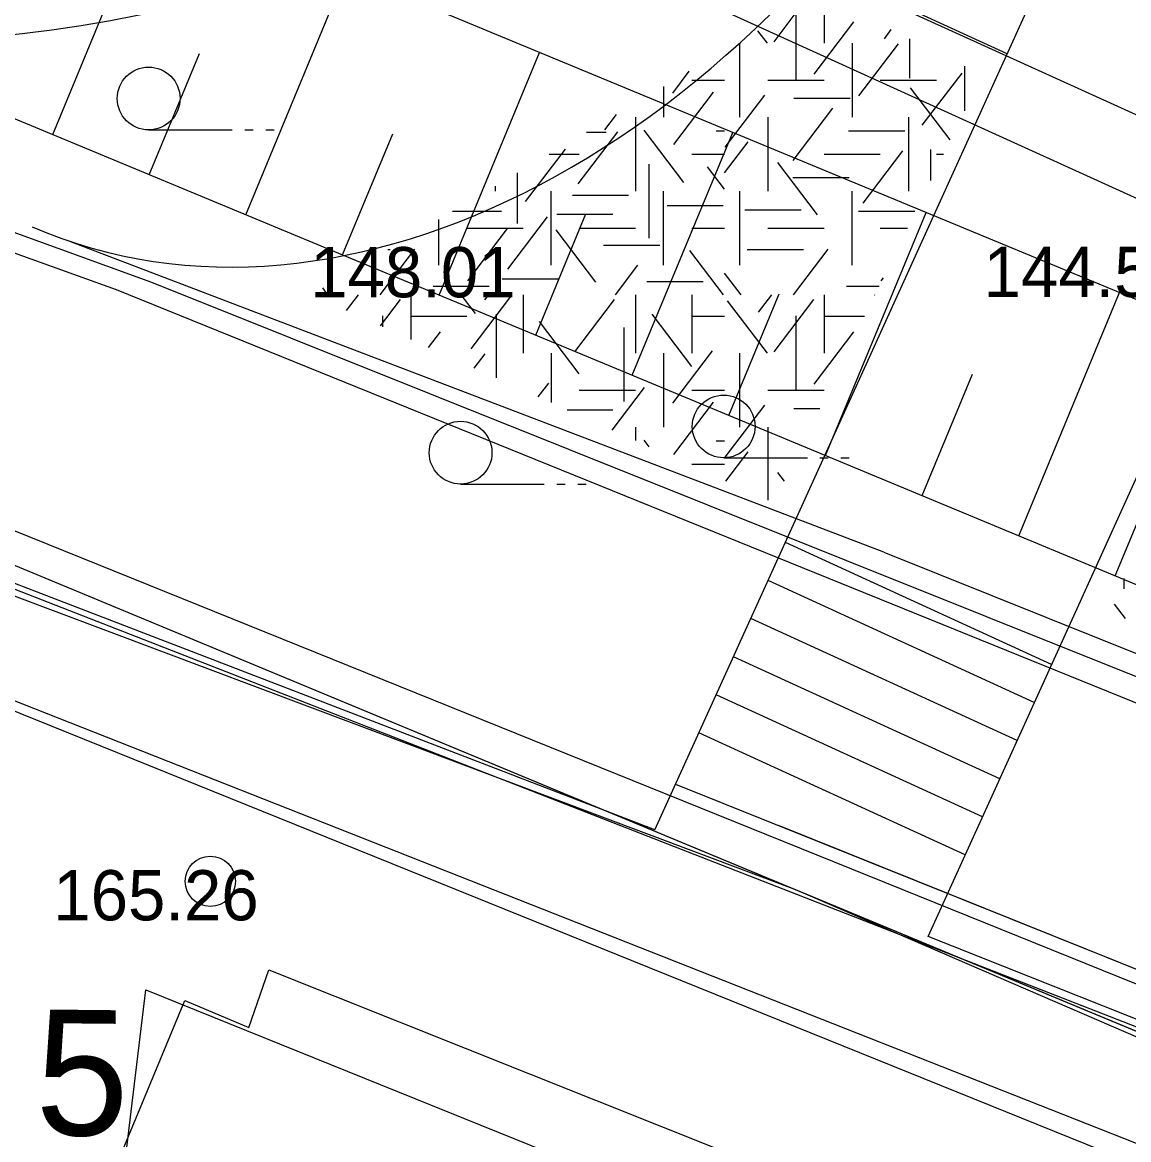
# Model space of a CAD drawing. Extents: x 419677 to 421689, y 4450851 to 4452923.
# Drawn here: x 420288.96 to 420315.4, y 4451951.82 to 4451978.52 of the extents above; entities that cross this region are included whole.
import ezdxf

# ---------------------------------------------------------------- set-up
doc = ezdxf.new("R2010")
doc.units = 0
for name, color, linetype in [('AA_HH', 7, 'Continuous'), ('Level 10', 7, 'Continuous'), ('Level 15', 7, 'Continuous'), ('Level 20', 7, 'Continuous'), ('Level 27', 7, 'Continuous'), ('Level 41', 7, 'Continuous'), ('Level 44', 7, 'Continuous'), ('Level 62', 7, 'Continuous'), ('Level 9', 7, 'Continuous'), ('MULKIYET SINIRI', 7, 'Continuous')]:
    doc.layers.add(name, color=color, linetype=linetype)

msp = doc.modelspace()

# ---------------------------------------------------------------- linework, layer by layer
at = {"layer": 'AA_HH'}
for p, q in [((420289.683, 4451975.836), (420292.08, 4451981.624)), ((420294.301, 4451973.918), (420296.7, 4451979.711)), ((420291.992, 4451974.877), (420293.191, 4451977.772)), ((420298.919, 4451972.001), (420301.319, 4451977.798)), ((420291.977, 4451975.949), (420293.977, 4451975.949)), ((420294.277, 4451975.949), (420294.477, 4451975.949)), ((420294.777, 4451975.949), (420294.977, 4451975.949)), ((420296.61, 4451972.96), (420297.81, 4451975.857)), ((420303.537, 4451970.084), (420305.939, 4451975.885)), ((420301.228, 4451971.043), (420302.429, 4451973.942)), ((420308.155, 4451968.167), (420310.559, 4451973.972)), ((420305.846, 4451969.125), (420307.047, 4451972.027)), ((420312.773, 4451966.249), (420315.178, 4451972.06)), ((420310.464, 4451967.208), (420311.666, 4451970.112)), ((420305.721, 4451968.112), (420307.721, 4451968.112)), ((420308.021, 4451968.112), (420308.221, 4451968.112)), ((420308.521, 4451968.112), (420308.721, 4451968.112)), ((420315.082, 4451965.291), (420316.285, 4451968.197)), ((420299.433, 4451967.484), (420301.433, 4451967.484)), ((420301.733, 4451967.484), (420301.933, 4451967.484)), ((420302.233, 4451967.484), (420302.433, 4451967.484))]:
    msp.add_line(p, q, dxfattribs=at)
for points in [[(420469.177, 4451906.353), (420425.667, 4451926.116), (420388.468, 4451943.011), (420341.767, 4451964.431), (420293.243, 4451986.453), (420255.412, 4452003.928)], [(420254.632, 4452002.39), (420271.038, 4451994.787), (420291.492, 4451985.31), (420303.504, 4451979.811), (420326.164, 4451969.517), (420347.575, 4451959.922), (420369.002, 4451949.737), (420385.167, 4451942.517), (420400.513, 4451935.409), (420415.08, 4451929), (420436.563, 4451919.226), (420459.524, 4451908.625), (420480.314, 4451899.212), (420495.263, 4451892.493)], [(420454.359, 4451909.748), (420418.625, 4451925.954), (420370.966, 4451947.229), (420330.993, 4451965.511), (420285.339, 4451984.415), (420255.675, 4451995.858), (420254.818, 4451996.216), (420252.115, 4451997.471)], [(420250.132, 4451994.063), (420261.301, 4451988.118), (420286.761, 4451977.049), (420322.451, 4451962.231), (420349.399, 4451950.546), (420385.854, 4451936.341), (420416.268, 4451924.288), (420449.542, 4451911.181), (420454.449, 4451909.721)], [(420241.052, 4451984.94), (420251.753, 4451983.621), (420261.352, 4451981.764), (420270.412, 4451979.548), (420279.858, 4451976.733), (420292.047, 4451972.313), (420315.298, 4451962.995), (420332.479, 4451956.177), (420346.933, 4451950.612), (420367.706, 4451942.214), (420387.741, 4451934.401), (420406.537, 4451927.02), (420425.964, 4451919.321), (420444.477, 4451912.185), (420464.01, 4451904.218), (420479.836, 4451897.866), (420495.475, 4451891.989), (420510.732, 4451885.251), (420532.559, 4451876.166), (420542.347, 4451872.342)], [(420271.403, 4451978.695), (420279.405, 4451976.372), (420291.203, 4451972.134), (420316.721, 4451961.79), (420338.013, 4451953.585), (420358.938, 4451945.013), (420382.624, 4451935.8), (420407.406, 4451926.131)], [(420390.75, 4451923.523), (420355.577, 4451937.004), (420307.443, 4451957.787), (420280.515, 4451967.9), (420273.647, 4451970.301), (420269.934, 4451971.02), (420261.568, 4451972.752), (420253.278, 4451973.826), (420241.307, 4451974.471), (420234.881, 4451973.555), (420234.717, 4451973.483)]]:
    msp.add_lwpolyline(points, dxfattribs=at)
for points in [[(420288.544, 4451940.705), (420286.365, 4451941.471), (420286.206, 4451948.679), (420287.779, 4451962.696), (420333.817, 4451944.538), (420332.311, 4451940.928), (420331.824, 4451939.351), (420333.066, 4451938.835), (420329.258, 4451929.421), (420328.406, 4451927.707), (420326.802, 4451928.337), (420325.749, 4451925.361)], [(420332.311, 4451940.928), (420331.824, 4451939.351), (420333.066, 4451938.835), (420329.258, 4451929.421), (420327.786, 4451930.122), (420327.166, 4451928.687), (420289.798, 4451943.988), (420288.544, 4451940.705), (420286.365, 4451941.471), (420287.999, 4451946.039), (420288.868, 4451945.556), (420292.839, 4451955.141), (420294.372, 4451954.497), (420294.853, 4451955.878)]]:
    msp.add_lwpolyline(points, close=True, dxfattribs=at)
for centre in [(420291.977, 4451976.699), (420305.721, 4451968.862), (420299.433, 4451968.234)]:
    msp.add_circle(centre, 0.75, dxfattribs=at)
at = {"layer": 'Level 10'}
msp.add_lwpolyline([(420320.676, 4451952.286), (420287.846, 4451965.918), (420283.914, 4451959.364), (420283.477, 4451950.626), (420231.702, 4451965.918)], dxfattribs=at)
at = {"layer": 'Level 15'}
msp.add_lwpolyline([(420414.132, 4451911.018), (420415.765, 4451915.419), (420282.101, 4451967.569), (420224.504, 4451969.178), (420220.055, 4451958.563), (420205.131, 4451843.779), (420215.712, 4451841.911), (420221.376, 4451877.395), (420222.223, 4451877.252)], dxfattribs=at)
at = {"layer": 'Level 20'}
msp.add_lwpolyline([(420290.535, 4451943.966), (420291.908, 4451955.394), (420333.973, 4451938.404)], dxfattribs=at)
msp.add_lwpolyline([(420290.535, 4451943.966), (420291.908, 4451955.394), (420333.973, 4451938.404)], dxfattribs=at)
at = {"layer": 'Level 27'}
msp.add_lwpolyline([(420248.61, 4451958.613), (420253.146, 4451957.391), (420268.822, 4451952.909), (420285.985, 4451948.012), (420287.724, 4451962.476), (420333.69, 4451943.911), (420338.452, 4451942.062), (420340.782, 4451941.146)], dxfattribs=at)
msp.add_lwpolyline([(420248.61, 4451958.613), (420253.146, 4451957.391), (420268.822, 4451952.909), (420285.985, 4451948.012), (420287.724, 4451962.476), (420333.69, 4451943.911), (420338.452, 4451942.062), (420340.782, 4451941.146)], dxfattribs=at)
msp.add_lwpolyline([(420248.61, 4451958.613), (420253.146, 4451957.391), (420268.822, 4451952.909), (420285.985, 4451948.012), (420287.724, 4451962.476), (420333.69, 4451943.911), (420338.452, 4451942.062), (420340.782, 4451941.146)], dxfattribs=at)
at = {"layer": 'Level 41'}
for p, q in [((420308.12, 4451979.148), (420308.12, 4451978.021)), ((420306.925, 4451978.056), (420307.598, 4451978.943)), ((420307.445, 4451978.852), (420307.445, 4451977.15)), ((420307.885, 4451977.284), (420308.834, 4451978.534)), ((420306.765, 4451978.021), (420306.54, 4451978.317)), ((420309.562, 4451978.125), (420309.728, 4451978.344)), ((420306.106, 4451976.254), (420306.106, 4451978.021)), ((420308.792, 4451978.021), (420308.792, 4451976.254)), ((420308.951, 4451976.759), (420309.9, 4451978.009)), ((420310.162, 4451978.127), (420310.162, 4451977.185)), ((420311.478, 4451977.469), (420311.478, 4451976.406)), ((420304.505, 4451976.828), (420304.9, 4451977.349)), ((420310.468, 4451976.058), (420311.419, 4451977.307)), ((420304.285, 4451976.985), (420304.285, 4451976.254)), ((420304.285, 4451976.985), (420304.285, 4451976.254)), ((420304.956, 4451977.137), (420305.744, 4451977.137)), ((420306.777, 4451977.137), (420308.12, 4451977.137)), ((420309.463, 4451977.137), (420310.806, 4451977.137)), ((420311.134, 4451975.708), (420310.184, 4451976.957)), ((420304.531, 4451975.602), (420305.481, 4451976.851)), ((420305.754, 4451975.533), (420306.703, 4451976.782)), ((420307.401, 4451976.703), (420308.744, 4451976.703)), ((420307.379, 4451975.216), (420308.328, 4451976.466)), ((420302.88, 4451975.953), (420303.158, 4451976.319)), ((420303.613, 4451976.254), (420303.613, 4451974.487)), ((420306.777, 4451976.254), (420306.777, 4451974.487)), ((420310.135, 4451976.254), (420310.135, 4451974.487)), ((420302.24, 4451974.656), (420303.19, 4451975.906)), ((420302.443, 4451975.897), (420302.913, 4451975.897)), ((420304.77, 4451974.69), (420303.821, 4451975.939)), ((420305.54, 4451975.93), (420305.744, 4451975.93)), ((420308.707, 4451975.93), (420310.05, 4451975.93)), ((420305.744, 4451974.924), (420306.303, 4451975.66)), ((420300.988, 4451974.236), (420301.937, 4451975.485)), ((420301.552, 4451975.37), (420302.27, 4451975.37)), ((420304.956, 4451975.37), (420305.744, 4451975.37)), ((420308.12, 4451975.37), (420309.463, 4451975.37)), ((420309.056, 4451974.2), (420310.006, 4451975.45)), ((420310.667, 4451975.482), (420310.667, 4451974.738)), ((420310.806, 4451975.37), (420310.974, 4451975.37)), ((420303.931, 4451975.132), (420303.931, 4451973.364)), ((420305.744, 4451974.53), (420305.338, 4451975.064)), ((420307.964, 4451973.919), (420307.015, 4451975.169)), ((420300.788, 4451974.919), (420300.788, 4451973.714)), ((420307.374, 4451974.81), (420308.717, 4451974.81)), ((420300.256, 4451974.605), (420300.256, 4451974.487)), ((420301.599, 4451972.719), (420301.599, 4451974.487)), ((420304.285, 4451972.719), (420304.285, 4451974.487)), ((420306.106, 4451972.719), (420306.106, 4451974.487)), ((420308.792, 4451972.719), (420308.792, 4451974.487)), ((420302.104, 4451974.389), (420303.447, 4451974.389)), ((420299.24, 4451974.004), (420300.41, 4451974.004)), ((420304.367, 4451974.144), (420305.71, 4451974.144)), ((420306.229, 4451974.038), (420307.572, 4451974.038)), ((420308.946, 4451974.004), (420310.289, 4451974.004)), ((420298.913, 4451972.719), (420298.913, 4451973.811)), ((420300.563, 4451972.622), (420301.512, 4451973.872)), ((420301.73, 4451973.933), (420303.073, 4451973.933)), ((420299.584, 4451973.603), (420300.927, 4451973.603)), ((420299.603, 4451972.343), (420300.552, 4451973.592)), ((420302.666, 4451972.308), (420301.716, 4451973.557)), ((420302.27, 4451973.603), (420303.613, 4451973.603)), ((420304.956, 4451973.603), (420305.744, 4451973.603)), ((420306.777, 4451973.603), (420308.12, 4451973.603)), ((420309.463, 4451973.603), (420310.115, 4451973.603)), ((420302.849, 4451973.196), (420304.192, 4451973.196)), ((420297.512, 4451972.01), (420298.341, 4451973.101)), ((420297.696, 4451973.092), (420297.746, 4451973.092)), ((420305.715, 4451972.01), (420304.913, 4451973.066)), ((420306.283, 4451973.092), (420307.625, 4451973.092)), ((420307.391, 4451972.01), (420308.22, 4451973.101)), ((420303.132, 4451972.01), (420303.669, 4451972.716)), ((420300.426, 4451972.391), (420301.769, 4451972.391)), ((420306.138, 4451972.01), (420305.744, 4451972.528)), ((420309.482, 4451972.343), (420309.537, 4451972.416)), ((420296.259, 4451972.01), (420296.137, 4451972.171)), ((420298.774, 4451972.216), (420300.117, 4451972.216)), ((420303.888, 4451972.322), (420305.231, 4451972.322)), ((420308.653, 4451972.216), (420309.44, 4451972.216)), ((420296.705, 4451971.632), (420296.992, 4451972.01)), ((420297.517, 4451971.267), (420297.995, 4451971.897)), ((420298.241, 4451972.01), (420298.241, 4451970.941)), ((420299.79, 4451971.558), (420299.446, 4451972.01)), ((420299.683, 4451970.716), (420300.633, 4451971.966)), ((420300.016, 4451971.89), (420300.107, 4451972.01)), ((420300.927, 4451972.01), (420300.927, 4451970.612)), ((420302.16, 4451970.647), (420303.109, 4451971.897)), ((420303.613, 4451972.01), (420303.613, 4451970.612)), ((420304.956, 4451972.01), (420304.956, 4451970.612)), ((420304.956, 4451972.01), (420304.956, 4451970.612)), ((420306.765, 4451970.612), (420305.816, 4451971.862)), ((420306.554, 4451971.593), (420306.871, 4451972.01)), ((420306.925, 4451970.647), (420307.874, 4451971.897)), ((420308.12, 4451972.01), (420308.12, 4451970.612)), ((420309.334, 4451971.998), (420309.325, 4451972.01)), ((420300.283, 4451971.543), (420300.283, 4451970.022)), ((420304.957, 4451970.296), (420304.008, 4451971.545)), ((420297.566, 4451971.508), (420297.566, 4451971.245)), ((420298.241, 4451971.496), (420299.584, 4451971.496)), ((420302.267, 4451970.121), (420301.318, 4451971.37)), ((420304.956, 4451971.496), (420305.744, 4451971.496)), ((420307.445, 4451971.508), (420307.445, 4451969.741)), ((420308.12, 4451971.496), (420309.09, 4451971.496)), ((420298.669, 4451970.748), (420298.955, 4451971.125)), ((420303.331, 4451971.222), (420303.331, 4451969.455)), ((420307.885, 4451969.875), (420308.834, 4451971.125)), ((420299.761, 4451970.257), (420300.021, 4451970.6)), ((420301.599, 4451970.612), (420301.599, 4451969.43)), ((420304.285, 4451970.612), (420304.285, 4451968.845)), ((420304.285, 4451970.612), (420304.285, 4451968.845)), ((420304.505, 4451969.419), (420305.454, 4451970.669)), ((420306.106, 4451968.845), (420306.106, 4451970.612)), ((420301.289, 4451969.569), (420301.54, 4451969.898)), ((420302.27, 4451969.728), (420303.613, 4451969.728)), ((420303.055, 4451968.774), (420303.829, 4451969.794)), ((420304.956, 4451969.728), (420305.744, 4451969.728)), ((420306.777, 4451969.728), (420308.12, 4451969.728)), ((420304.531, 4451968.193), (420305.481, 4451969.442)), ((420301.98, 4451969.258), (420303.073, 4451969.258)), ((420305.754, 4451968.124), (420306.703, 4451969.373)), ((420307.401, 4451969.294), (420308.019, 4451969.294)), ((420303.613, 4451968.845), (420303.613, 4451968.523)), ((420306.777, 4451968.845), (420306.777, 4451967.099)), ((420303.937, 4451968.377), (420303.821, 4451968.53)), ((420305.54, 4451968.521), (420305.744, 4451968.521)), ((420305.772, 4451967.552), (420306.303, 4451968.251)), ((420304.956, 4451967.961), (420305.744, 4451967.961)), ((420307.172, 4451967.553), (420307.015, 4451967.76)), ((420315.296, 4451964.98), (420315.296, 4451965.228)), ((420315.328, 4451964.271), (420315.065, 4451964.617))]:
    msp.add_line(p, q, dxfattribs=at)
at = {"layer": 'Level 44'}
msp.add_circle((420293.451, 4451957.991), 0.6, dxfattribs=at)
msp.add_circle((420293.451, 4451957.991), 0.6, dxfattribs=at)
at = {"layer": 'Level 62'}
for p, q in [((420305.615, 4451962.606), (420328.411, 4452012.846)), ((420312.135, 4451960.035), (420334.348, 4452008.992)), ((420312.494, 4451977.768), (420307.934, 4451979.86)), ((420312.494, 4451977.768), (420307.934, 4451979.86)), ((420312.494, 4451977.768), (420307.934, 4451979.86)), ((420309.547, 4451965.857), (420290.096, 4451973.285)), ((420313.559, 4451963.174), (420307.196, 4451966.091)), ((420313.559, 4451963.174), (420307.196, 4451966.091)), ((420313.559, 4451963.174), (420307.196, 4451966.091)), ((420309.547, 4451965.857), (420356.221, 4451947.097)), ((420304.078, 4451959.219), (420288.136, 4451965.357)), ((420313.146, 4451962.264), (420306.783, 4451965.18)), ((420313.146, 4451962.264), (420306.783, 4451965.18)), ((420313.146, 4451962.264), (420306.783, 4451965.18)), ((420312.733, 4451961.353), (420306.37, 4451964.269)), ((420312.733, 4451961.353), (420306.37, 4451964.269)), ((420312.733, 4451961.353), (420306.37, 4451964.269)), ((420312.32, 4451960.443), (420305.957, 4451963.359)), ((420312.32, 4451960.443), (420305.957, 4451963.359)), ((420312.32, 4451960.443), (420305.957, 4451963.359)), ((420304.078, 4451959.219), (420305.615, 4451962.606)), ((420305.615, 4451962.606), (420305.615, 4451962.606)), ((420311.907, 4451959.532), (420305.543, 4451962.448)), ((420311.907, 4451959.532), (420305.543, 4451962.448)), ((420311.907, 4451959.532), (420305.543, 4451962.448)), ((420311.493, 4451958.621), (420305.13, 4451961.537)), ((420311.493, 4451958.621), (420305.13, 4451961.537)), ((420311.493, 4451958.621), (420305.13, 4451961.537)), ((420304.568, 4451960.315), (420353.629, 4451940.595)), ((420310.609, 4451956.672), (420312.135, 4451960.035)), ((420307.021, 4451959.329), (420353.629, 4451940.595)), ((420307.021, 4451959.329), (420353.629, 4451940.595)), ((420425.203, 4451911.087), (420310.609, 4451956.672))]:
    msp.add_line(p, q, dxfattribs=at)
msp.add_lwpolyline([(420285.948, 4451967.507), (420335.163, 4451947.63), (420339.908, 4451945.788), (420371.039, 4451933.55), (420393.013, 4451924.881), (420415.879, 4451915.628)], dxfattribs=at)
msp.add_ellipse((420298.501, 4451995.253), major_axis=(-9.31, -21.622), ratio=0.698592, start_param=0, end_param=2.848642, dxfattribs=at)
msp.add_open_spline([(420301.269, 4451982.918), (420289.191, 4451973.63), (420250.246, 4451985.779), (420242.55, 4451988.153), (420241.405, 4451988.503)], degree=3, dxfattribs=at)
at = {"layer": 'Level 9'}
msp.add_lwpolyline([(420425.574, 4451910.283), (420391.286, 4451924.082), (420343.881, 4451942.651), (420287.846, 4451965.918), (420283.914, 4451959.364), (420283.477, 4451950.626), (420231.702, 4451965.918), (420228.644, 4451941.45), (420224.602, 4451910.32), (420222.636, 4451894.154), (420216.956, 4451865.1), (420209.201, 4451819.114), (420204.832, 4451797.924), (420203.303, 4451783.287), (420202.429, 4451776.297), (420195.86, 4451755.756)], dxfattribs=at)
msp.add_lwpolyline([(420425.574, 4451910.283), (420391.286, 4451924.082), (420343.881, 4451942.651), (420287.846, 4451965.918), (420283.914, 4451959.364), (420283.477, 4451950.626), (420231.702, 4451965.918), (420228.644, 4451941.45), (420224.602, 4451910.32), (420222.636, 4451894.154), (420216.956, 4451865.1), (420209.201, 4451819.114), (420204.832, 4451797.924), (420203.303, 4451783.287), (420202.429, 4451776.297), (420195.86, 4451755.756)], dxfattribs=at)
at = {"layer": 'MULKIYET SINIRI'}
msp.add_lwpolyline([(420284.013, 4451934.694), (420285.171, 4451941.809), (420285.985, 4451948.012), (420287.724, 4451962.476), (420333.69, 4451943.911), (420337.904, 4451942.275), (420338.452, 4451942.062), (420335.919, 4451921.425), (420335.65, 4451919.233)], close=True, dxfattribs=at)
msp.add_lwpolyline([(420284.013, 4451934.694), (420285.171, 4451941.809), (420285.985, 4451948.012), (420287.724, 4451962.476), (420333.69, 4451943.911), (420337.904, 4451942.275), (420338.452, 4451942.062), (420335.919, 4451921.425), (420335.65, 4451919.233)], close=True, dxfattribs=at)

# ---------------------------------------------------------------- texts
at = {"layer": 'AA_HH'}
for s, p in [('148.01 ', (420295.838, 4451971.948)), ('144.55 ', (420311.934, 4451971.954))]:
    msp.add_text(s, height=1.2, rotation=359.9981, dxfattribs=at).set_placement(p)
msp.add_text('165.26', height=1.2, dxfattribs=at).set_placement((420289.699, 4451957.057))
at = {"layer": 'Level 20'}
msp.add_text('5', height=3, rotation=359.4141, dxfattribs=at).set_placement((420289.26, 4451951.929))
msp.add_text('5', height=3, rotation=359.4141, dxfattribs=at).set_placement((420289.26, 4451951.929))

doc.saveas('drawing.dxf')
